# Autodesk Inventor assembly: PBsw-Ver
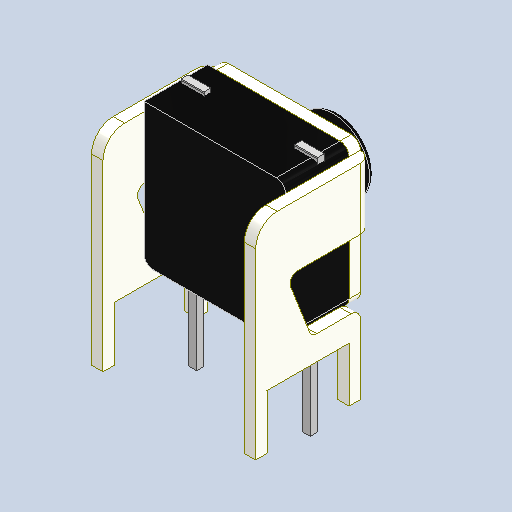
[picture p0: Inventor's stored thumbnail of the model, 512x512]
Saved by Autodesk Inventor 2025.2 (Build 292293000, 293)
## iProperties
Created: 2025-04
Part Number: PBsw-Ver
Description: PART--DESC
Document SubType Name: Assembly
Designer: BennF
Author: BennF
Revision Number: NONE
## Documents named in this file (4)
- C:\Users\BennF\Nextcloud\Benutzer\CNC JarBeRi\existing parts\Electronics\RepRap A4988 Shied (USE WITHOUT ARDUINO)\reprap-a4988-1.snapshot.1\RepRap\RepRap\PBsw-Ver.iam
- C:\Users\BennF\Nextcloud\Benutzer\CNC JarBeRi\existing parts\Electronics\RepRap A4988 Shied (USE WITHOUT ARDUINO)\reprap-a4988-1.snapshot.1\RepRap\RepRap\frame.ipt
- C:\Users\BennF\Nextcloud\Benutzer\CNC JarBeRi\existing parts\Electronics\RepRap A4988 Shied (USE WITHOUT ARDUINO)\reprap-a4988-1.snapshot.1\RepRap\RepRap\pin17.ipt
- C:\Users\BennF\Nextcloud\Benutzer\CNC JarBeRi\existing parts\Electronics\RepRap A4988 Shied (USE WITHOUT ARDUINO)\reprap-a4988-1.snapshot.1\RepRap\RepRap\cap.ipt
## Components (3 placed, 3 different names)
1. frame
2. pin17
3. cap
